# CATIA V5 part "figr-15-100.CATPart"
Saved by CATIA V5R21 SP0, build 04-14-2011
Part number: Part1
Bounding box of the stored display mesh (mm): x -52.43 to 60.529, y -25.631 to 32.893, z 0 to 1
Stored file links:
  D:\CATIA V5R21 E-RESOURCES\CATIA-V5R21\catia-v5r21-prt\c15-catia-v5r20-prt\c15-catia-v5r21-figr-15-100.CATPart
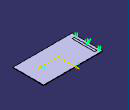
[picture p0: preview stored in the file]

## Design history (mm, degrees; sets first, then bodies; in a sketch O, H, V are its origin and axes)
SheetMetalParameters1: Thickness 1, BendRadius 5, KFactor 0.5 {= log(min(100,max(20*SheetMetalParameters1.BendRadius,SheetMetalParameters1.Thickness)/SheetMetalParameters1.Thickness))/log(100)/2}, ReliefRadialLength 1, ReliefAxialLength 2, MinimumBendRadius 0
Body1 (main body)
  Sketch1 on xy-plane, origin (0, 0, 0), H (1, 0, 0), V (0, 1, 0)
    line L1 (-52.4297, 32.8934) -> (60.5286, 32.8934)
    line L2 (60.5286, 32.8934) -> (60.5286, -25.6312)
    line L3 (60.5286, -25.6312) -> (-52.4297, -25.6312)
    line L4 (-52.4297, -25.6312) -> (-52.4297, 32.8934)
    horizontal: L1 H, L3 H
    vertical: L2 V, L4 V
  Wall1: Thickness 1, Profile Sketch1
  Sketch2 on face of Wall1, origin (0, 0, 1), H (1, 0, 0), V (0, 1, 0)
    line L1 (-47.3159, -16.5837) -> (-43.073, -16.5837)
    line L2 (-43.073, -16.5837) -> (-43.073, 26.788)
    line L3 (-43.073, 26.788) -> (-47.3159, 26.788)
    line L4 (-47.3159, 26.788) -> (-47.3159, -16.5837)
    horizontal: L1 H, L3 H
    vertical: L2 V, L4 V
  d_Stamp1: Stamp_FilletRadius 2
